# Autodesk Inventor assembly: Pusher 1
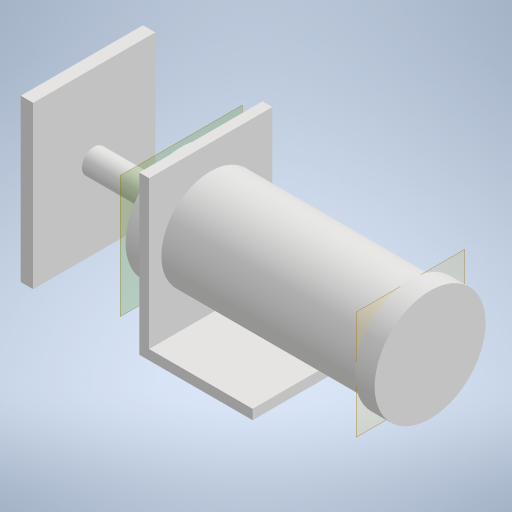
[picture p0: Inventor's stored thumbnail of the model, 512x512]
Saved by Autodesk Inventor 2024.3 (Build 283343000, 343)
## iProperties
Created: 2024-12
Part Number: Pusher 1
Document SubType Name: Assembly
Designer: ruhr
Author: ruhr
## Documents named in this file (7)
- C:\Users\ruhr\OneDrive - Mercantec\Dokumenter\DigiTwinVideo\Pusher 1.iam
- C:\Users\ruhr\OneDrive - Mercantec\Dokumenter\DigiTwinVideo\Barrel.ipt
- C:\Users\ruhr\OneDrive - Mercantec\Dokumenter\DigiTwinVideo\Back end cap.ipt
- C:\Users\ruhr\OneDrive - Mercantec\Dokumenter\DigiTwinVideo\Front end cap.ipt
- C:\Users\ruhr\OneDrive - Mercantec\Dokumenter\DigiTwinVideo\Rod.ipt
- C:\Users\ruhr\OneDrive - Mercantec\Dokumenter\DigiTwinVideo\Mounting bracet.ipt
- C:\Users\ruhr\OneDrive - Mercantec\Dokumenter\DigiTwinVideo\Pusher plate.ipt
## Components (6 placed, 6 different names)
1. Barrel:1 — Flush:1, Flush:2, Flush:3, Flush:4
2. Back end cap:1 — Flush:1, Flush:2
3. Front end cap:1 — Flush:3, Flush:4, Flush:5, Flush:6, Flush:7, Flush:8
4. Rod:1 — Flush:5, Flush:6, Flush:9
5. Mounting bracet:1 — Flush:7, Flush:8
6. Pusher plate:1 — Flush:9
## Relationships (9: Flush 9)
- Flush:1: Barrel:1 ↔ Back end cap:1
- Flush:2: Barrel:1 ↔ Back end cap:1
- Flush:3: Barrel:1 ↔ Front end cap:1
- Flush:4: Barrel:1 ↔ Front end cap:1
- Flush:5: Front end cap:1 ↔ Rod:1
- Flush:6: Front end cap:1 ↔ Rod:1
- Flush:7: Front end cap:1 ↔ Mounting bracet:1
- Flush:8: Front end cap:1 ↔ Mounting bracet:1
- Flush:9: Rod:1 ↔ Pusher plate:1
